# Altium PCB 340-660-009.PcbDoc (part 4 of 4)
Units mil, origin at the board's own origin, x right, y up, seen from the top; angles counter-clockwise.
Board outline 2755.91 x 2755.91 mil, 4 copper layers (Top Layer, Int1 (PWR), Int2 (GND), Bottom Layer), stack 53.912 mil thick; 183 components, 253 nets, 930 pads, 492 vias.
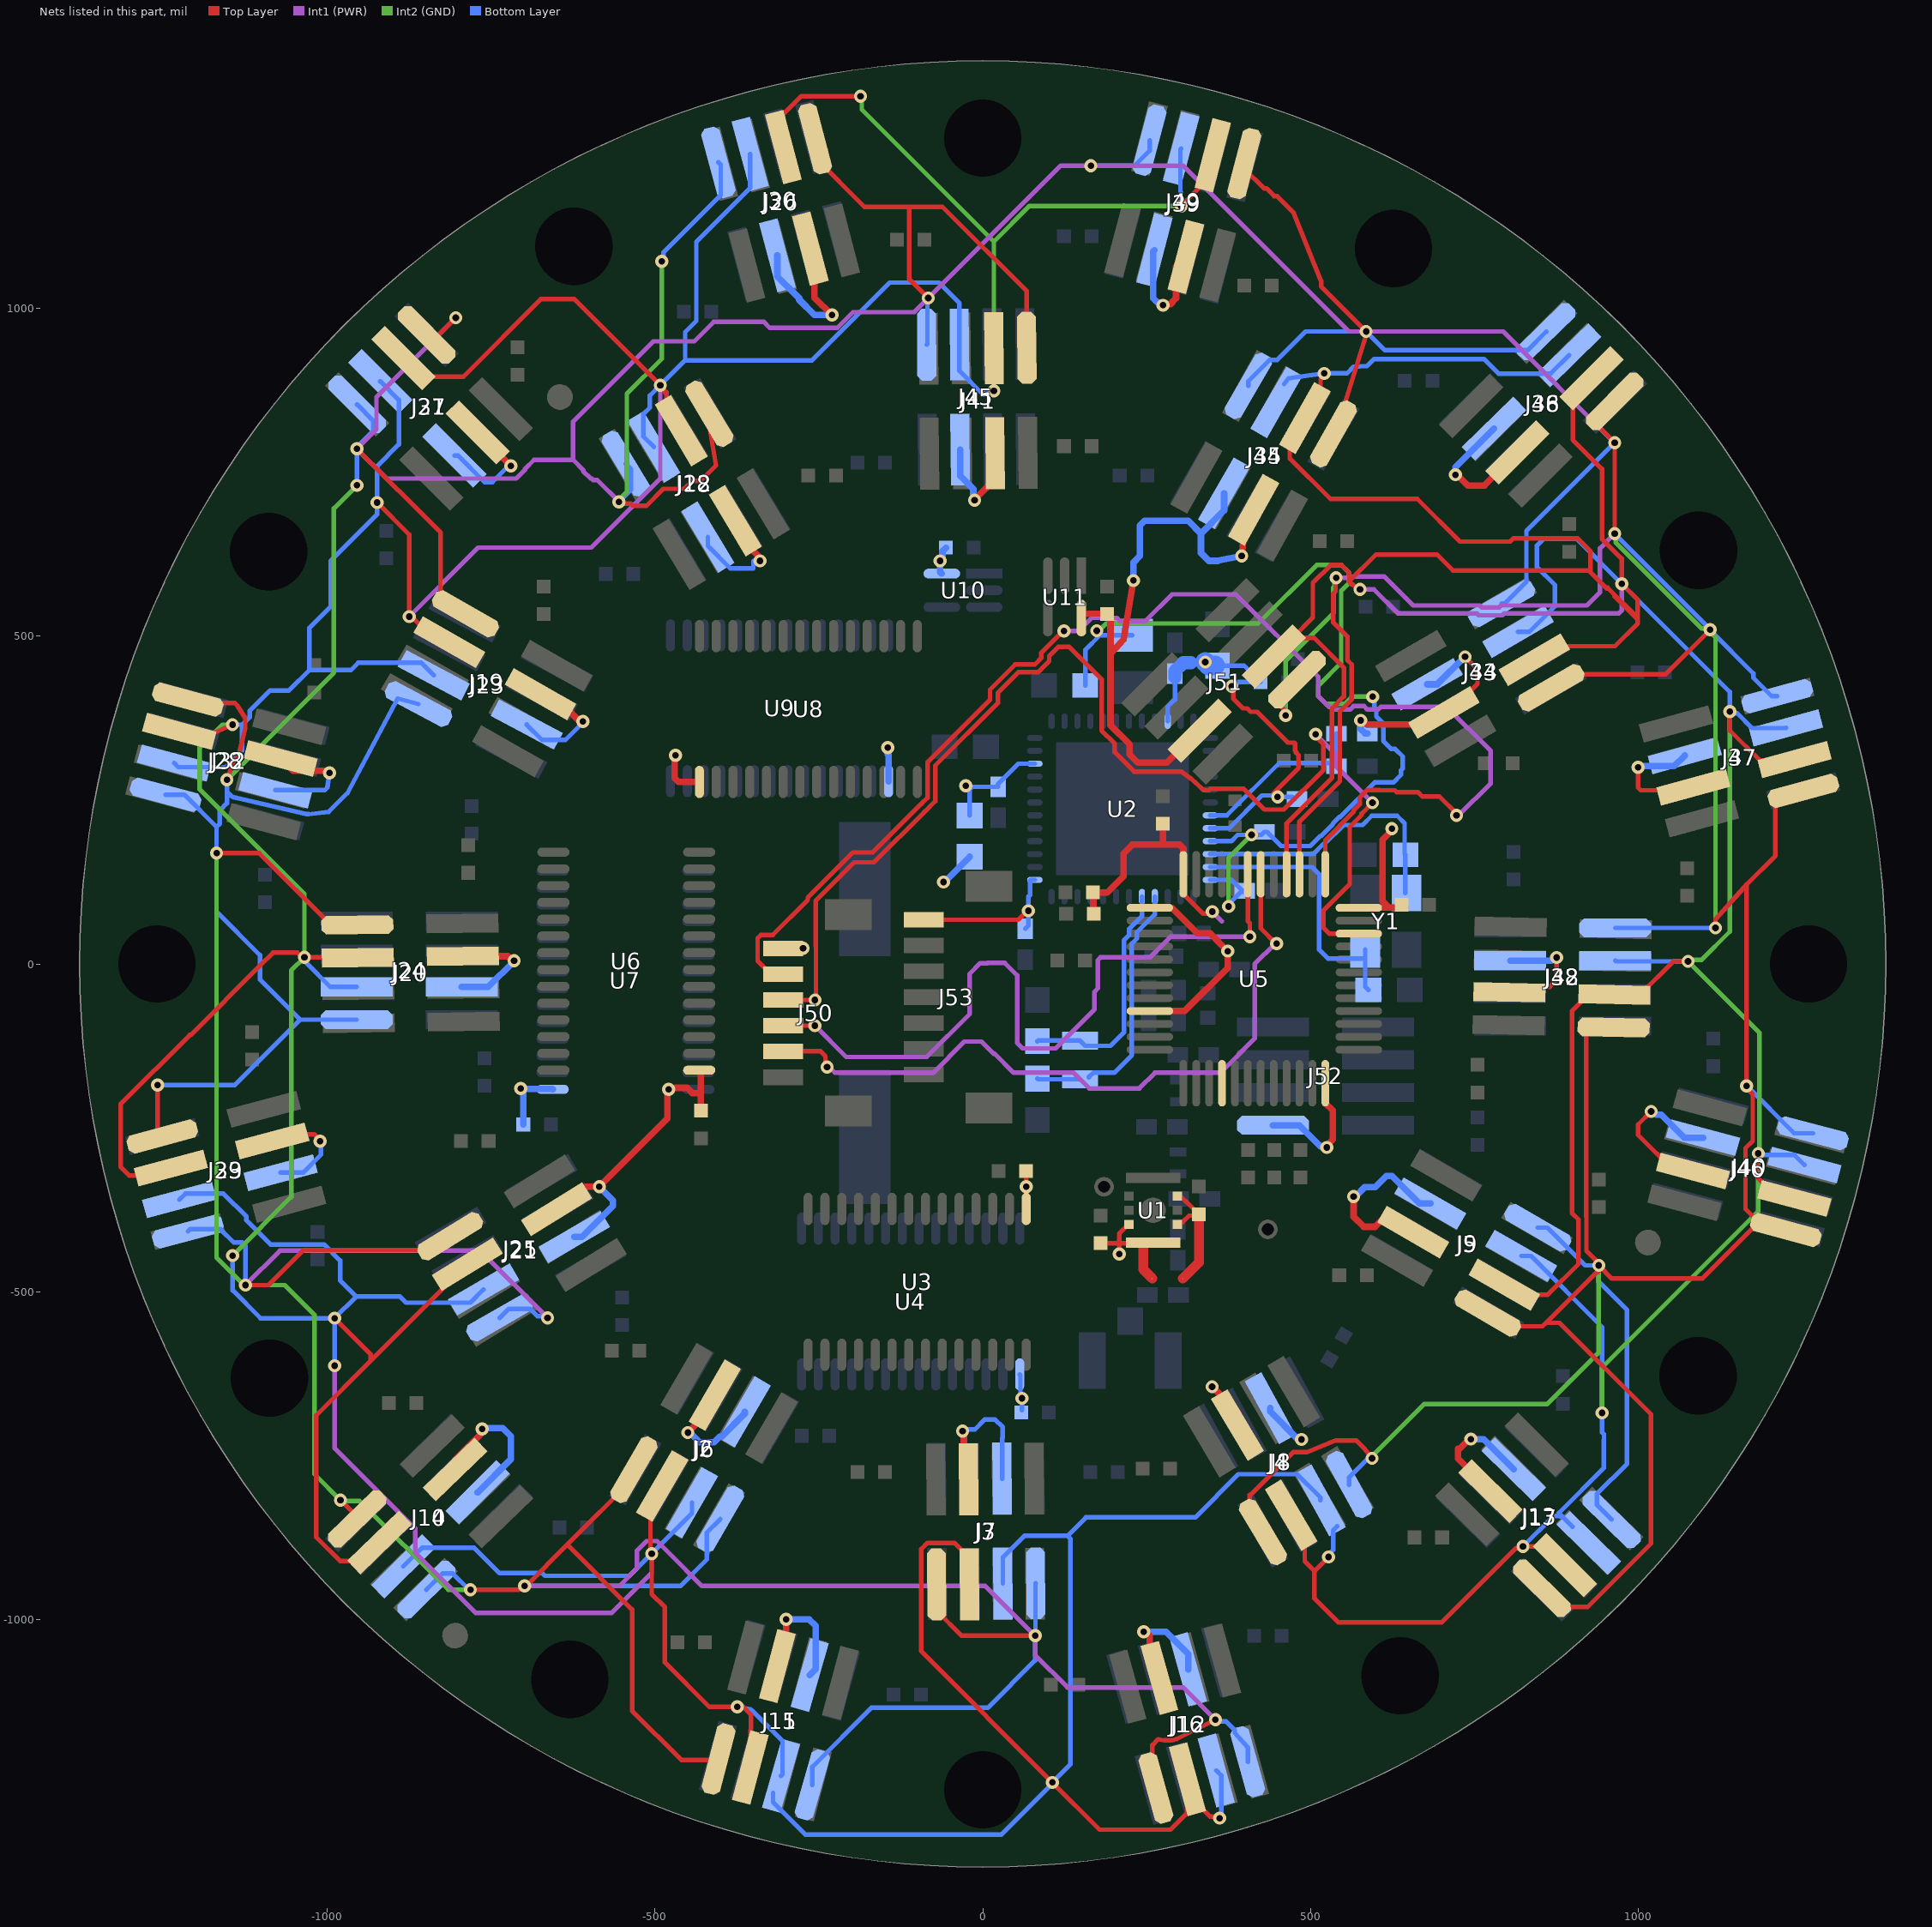
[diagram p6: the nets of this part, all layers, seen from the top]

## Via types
v1: diameter 20, hole 10, Top Layer to Bottom Layer, tented both sides, 489 vias
v2: diameter 20, hole 10, Top Layer to Bottom Layer, 3 vias

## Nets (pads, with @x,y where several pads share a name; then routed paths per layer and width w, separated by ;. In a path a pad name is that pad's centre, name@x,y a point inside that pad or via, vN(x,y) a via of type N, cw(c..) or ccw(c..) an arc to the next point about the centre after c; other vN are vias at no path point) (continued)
SPI_MISO: J2.3 J3.3 J4.3 J5.3 J6.3 J7.3 J8.3 J9.3 J10.3 J11.3 J12.3 J13.3 J14.3 J15.3 J16.3 J17.3 J18.3 J19.3 J20.3 J21.3 J22.3 J23.3 J24.3 J25.3 J26.3 J27.3 J28.3 J29.3 J30.3 J31.3 J32.3 J33.3 J34.3 J35.3 J36.3 J37.3 J38.3 J39.3 J40.3 J41.3 J42.3 J43.3 J44.3 J45.3 J46.3 J47.3 J48.3 J49.3 J51.3 U5.40 | length 20691.8
  Top Layer w7: J29.3@-1238.86,-311.6 -1250.18,-322.92 -1302.08,-322.92 -1315.49,-309.51 -1315.49,-213.91 -1209.93,-108.35 -1208.35,-108.35 -1102.79,-2.79 -1102.79,-2.63 -1082.87,17.29 -1045.81,17.29 -1040.95,12.43 v1@-1037.43,12.43 ; J28.3@-1225.94,354.86 -1173.4,352.26 v1(-1144.77,365) ; v1(-1035,10) -953.93,10 J20.3@-953.48,9.55 ; v1(-989,-540.5) -934.11,-595.39 -934.11,-605.89 ; v1(-924,704) -875,655 v1(-875,530) -871.55,530 -832.49,490.94 J19.3@-814.01,490.94 ; J10.3@-919.96,-882.76 -948.02,-910.83 -980.59,-910.83 -1017,-874.42 -1017,-688.79 -934.11,-605.89 ; J27.3@-855.38,895.88 -792.64,895.88 -674.01,1014.5 -623.5,1014.5 -490.71,881.71 -490.71,880.53 -482.58,872.4 -482.58,836.09 J18.3@-460.14,813.65 ; J21.3@-786.43,-458.21 -934.11,-605.89 ; v1(-492,883) -492,879.48 -484.46,871.94 ; J2.3@-488.94,-796.68 -507.08,-814.82 -507.08,-897.92 v1(-505,-900) -505,-961.5 -485,-981.5 -485,-1065.58 -417.02,-1133.56 v1(-374.7,-1133.56) -365.06,-1133.56 -362.97,-1135.65 -353.6,-1145.3 -353.6,-1148.19 -353.6,-1148.25 J11.3@-354.76,-1225.99 ; J26.3@-304.27,1246.24 -304.27,1296.45 -276.72,1324 v1(-186.5,1324) ; J3.3@-20.38,-946.49 -20.38,-906.43 -43.43,-883.38 -84.44,-883.38 -93.79,-892.73 -93.79,-1048.79 v1(106.21,-1248.79) 178.31,-1320.88 286.53,-1320.88 312.32,-1295.1 J12.3@312.32,-1266.25 ; v1(17,874.34) 17,939.26 J41.3@17.25,939.51 ; v1(302.95,1156.5) 302.95,1156.79 351,1204.83 J49.3@351,1233.85 ; J12.3@312.32,-1243.89 J12.3@312.32,-1266.25 ; v1(361.41,-1303.34) 358.93,-1300.85 346.92,-1300.85 J12.3@312.32,-1266.25 ; J51.3@444.33,468.97 J51.3@472.86,497.51 ; U5.40@463.6,136.8 463.6,214.54 533,283.93 533,389.97 551,407.97 551,452 505.49,497.51 J51.3@472.86,497.51 ; J4.3@470.63,-841.23 491.26,-861.85 491.26,-911.26 506.21,-926.21 ; v1(521,901) 521,897.48 515.5,891.98 515.5,856.86 468.43,809.8 468.43,771.57 530.5,709.5 663.08,709.5 728.08,644.5 804.84,644.5 809.84,649.5 907.52,649.5 927.23,629.79 927.23,597.77 ; v1(527.7,-904.73) 506.21,-926.21 ; v1(575.66,571.5) 572.14,571.5 564.11,579.53 562.5,579.53 558.7,583.34 ; J5.3@795.66,-489.42 810.84,-504.61 862.36,-504.61 909.02,-457.95 909.02,-390.01 899.07,-380.06 899.07,-72.02 924.26,-46.82 1003.19,-46.82 1053.96,3.95 v1(1076.17,3.95) ; v1(824.37,-888.73) 821.89,-891.22 813.78,-891.22 700.52,-1004.48 542.6,-1004.48 506.21,-968.1 506.21,-926.21 ; v1@824.45,-888.81 859.99,-888.81 J13.3@888.43,-917.25 ; J34.3@841.92,464.46 862.32,484.87 964.67,484.87 999.5,519.7 999.5,525.5 ; J48.3@928.97,893.64 900.44,865.1 900.44,799.56 944.83,755.17 944.83,648.51 975,618.35 v1(975,580) 999.5,555.5 999.5,527.92 ; 952.3,572.7 927.23,597.77 ; 953.51,573.91 999.5,527.92 ; 964.09,560.91 999.5,525.5 ; v1(1140,385) 1140,356.23 1185.84,310.39 1237.32,310.39 J47.3@1238.87,311.95 ; v1(1183.37,-289.11) 1180,-315 1180,-323.7 1214.07,-357.76 J46.3@1238.36,-357.76 ; J51.3@472.86,497.51 503.81,528.45 503.81,581.38 531.12,608.7 547.27,608.7 558.7,597.27 558.7,583.34 ; 558.7,583.34 599.86,624.5 693.22,624.5 717.38,600.34 924.66,600.34 927.23,597.77 ; 999.5,525.5 999.5,527.92
  Int1 (PWR) w7: v1(-989,-613) -989,-738.42 -865.96,-861.46 -865.96,-897.96 -773.92,-990 -566.16,-990 -505,-928.84 v1(-505,-900) ; v1(-875,530) -769.79,635.21 -597.21,635.21 -492,740.42 v1(-492,883) ; v1(575.66,571.5) 596.93,571.5 633.42,535 753.66,535 756.74,531.92 792.78,531.92 795.86,535 970.9,535 975,539.1 v1(975,580)
  Int2 (GND) w7: v1(-1144.77,365) -1160,365 -1195,330 -1195,266.79 -1035,106.79 v1(-1035,10) -1055,-10 -1055,-355.5 v1(-1144.5,-445) ; v1(-186.5,1324) -184.5,1322 -184.5,1303.5 17,1102 ; v1(17,874.34) 17,1102 ; v1(302.95,1156.5) 71.5,1156.5 17,1102 ; v1(945,-685) 945,-615.58 1183.37,-377.2 1183.37,-292.01 v1@1186.27,-289.11 ; v1(1076.17,3.95) 1078.32,6.1 1096.67,6.1 1140,49.42 v1(1140,385) ; v1@1077.93,2.19 1185,-104.88 1185,-287.48 v1(1183.37,-289.11)
  Bottom Layer w7: J32.3@-1233.86,306.55 -1227.68,300.37 -1155.07,300.37 -1130,325.44 -1130,365 ; J33.3@-1225.92,-359.88 -1216.54,-350.5 -1158.6,-350.5 -1123.52,-385.58 -1123.52,-390.97 -1086.49,-428 -1004.98,-428 -980.49,-452.49 -980.49,-483.01 -956,-507.5 ; v1(-1144.77,365) -1130,365 ; v1(-1144.5,-445) -1144.5,-498.08 -1102.08,-540.5 v1(-989,-540.5) ; v1(-1035,10) -1032.51,7.51 -1032.51,2.04 -995.47,-35 J24.3@-955.12,-35 ; v1(-989,-613) v1(-989,-540.5) ; J31.3@-919.33,888.97 -890.8,860.44 -890.8,792.76 -924,759.55 v1(-924,704) -924,686 -995,615 -995,545 -1027.31,512.69 -1027.31,448.5 ; J14.3@-884.14,-919.24 -855.67,-890.77 -775.89,-890.77 -737.17,-929.5 -672.02,-929.5 -668.02,-933.5 -538.92,-933.5 -443.66,-838.24 J6.3@-443.66,-821.83 ; J23.3@-837.48,440.52 -856.42,459.46 -952.83,459.46 -963.79,448.5 -1027.31,448.5 ; J25.3@-761.88,-496.71 -782.06,-516.89 -879.92,-516.89 -889.31,-507.5 -956,-507.5 ; J22.3@-501.69,788.76 -517.92,804.98 -517.92,838.91 -508.02,848.8 -508.02,866.98 v1(-492,883) -454,921 ; v1(-374.7,-1133.56) -354.3,-1137 -350.92,-1140.38 -305.58,-1185.72 -305.58,-1236.46 J15.3@-308.02,-1238.91 ; J30.3@-354.88,1235.92 -354.74,1235.77 -354.74,1184.05 -437,1101.79 -437,980.98 -454,963.98 -454,921 ; J15.3@-320,-1265 -320,-1278.86 -270.31,-1328.56 28.4,-1328.56 107.19,-1249.76 107.19,-1247.81 133.6,-1221.4 133.6,-876.6 129.5,-872.5 ; v1(17,874.34) 14.51,871.85 4.23,871.85 0.87,868.49 -35.5,904.86 -35.5,1008.08 -66.92,1039.5 -141.85,1039.5 -260.35,921 -454,921 ; J7.3@30.84,-945.4 30.84,-905.34 63.68,-872.5 129.5,-872.5 ; v1(302.95,1156.5) 302.95,1177 301.6,1178.36 301.6,1242.72 J39.3@302.95,1244.08 ; J16.3@356.31,-1230.52 363.9,-1238.11 363.9,-1300.85 v1(361.41,-1303.34) ; J44.3@460,885 466.43,893.48 479.12,895.23 516.92,900.44 517.48,901 555.8,901 566,911.2 586.2,912.2 597.51,923 764.7,923 787.01,900.68 866.5,900.68 J36.3@894.74,928.92 ; J8.3@515.33,-818.35 515.33,-814.21 479.73,-778.62 390.12,-778.62 324.24,-844.5 157.5,-844.5 129.5,-872.5 ; v1(527.7,-904.73) 527.7,-901.21 534.66,-894.24 534.66,-864.16 J8.3@540.79,-858.03 ; J43.3@816.88,506.71 834,506.71 873.04,545.76 873.04,578.15 845.5,605.69 845.5,638.08 856.92,649.5 905.5,649.5 v1(975,580) 1140,415 v1@1140,385.56 ; J9.3@821.76,-445.57 836.53,-445.57 945,-554.05 v1(945,-685) ; v1(824.37,-888.73) 869.39,-843.71 874.42,-842.44 875.87,-842.44 885.35,-844.03 ; J17.3@899.77,-858.45 885.35,-844.03 ; v1@948,-685 945,-688 945,-714.58 948,-717.58 947.83,-731.88 947.83,-768.89 879.02,-837.7 885.35,-844.03 ; J42.3@965.12,5 966.17,3.95 v1(1076.17,3.95) ; v1(1140,385) 1142.49,382.51 1151.07,382.51 1173.76,359.83 1225.11,359.83 J37.3@1225.62,360.34 ; v1(1183.37,-289.11) 1185.86,-291.6 1238.81,-291.6 J40.3@1253.86,-306.65 ; -1130,365 -1118.54,376.46 -1118.54,386 -1087.29,417.25 -1058.56,417.25 -1027.31,448.5 ; v1(-989,-540.5) -956,-507.5
SPI_SCLK: J2.1 J3.1 J4.1 J5.1 J6.1 J7.1 J8.1 J9.1 J10.1 J11.1 J12.1 J13.1 J14.1 J15.1 J16.1 J17.1 J18.1 J19.1 J20.1 J21.1 J22.1 J23.1 J24.1 J25.1 J26.1 J27.1 J28.1 J29.1 J30.1 J31.1 J32.1 J33.1 J34.1 J35.1 J36.1 J37.1 J38.1 J39.1 J40.1 J41.1 J42.1 J43.1 J44.1 J45.1 J46.1 J47.1 J48.1 J49.1 J51.1 U5.39 | length 21685.5
  Top Layer w7: v1(-1259,-185) -1259,-256.11 J29.1@-1251.81,-263.31 ; J28.1@-1213.01,403.16 -1208.12,398.27 -1141.43,398.27 -1137.33,394.16 -1125.27,375.14 -1125.27,359.82 -1132.88,328.07 -1134.9,320.55 -1145.07,304.28 v1(-1153.27,280.87) ; v1(-1169,169) -1103.97,169 -994.51,59.54 J20.1@-954.17,59.54 ; v1(-1125,-490) -1090,-490 -1036.84,-436.84 -833.86,-436.84 J21.1@-812.68,-415.66 ; v1(-980,-818) -954.73,-843.27 J10.1@-954.73,-846.84 ; v1(-955,786) -827.09,658.09 -827.09,567.13 -794.31,534.36 J19.1@-789.22,534.36 ; J27.1@-848.48,959.69 -847.26,958.47 -831.53,958.47 v1(-804,986) ; v1(-781.66,-954.68) -708.2,-954.68 -702.52,-949 v1(-699,-949) -696.94,-949 -633.97,-886.03 ; v1(-555,705) -552.51,702.51 -537.03,702.51 -533.58,699.06 -512.91,699.06 -487.16,724.81 -455.54,724.81 -443.35,737 -430.5,737 -407,760.5 -417.28,822 J18.1@-417.28,839.4 ; J2.1@-532.21,-771.63 -532.21,-784.28 -633.97,-886.03 ; J11.1@-403.08,-1213.14 -404.44,-1214.5 -460,-1214.5 -535,-1139.5 -535,-985 -633.97,-886.03 ; J26.1@-239.15,1242.26 J26.1@-255.93,1259.04 -255.93,1230.37 -180.57,1155 -112,1155 ; v1(-83,1016) -112,1045 -112,1155 ; J3.1@-70.37,-946.85 -70.37,-986.91 -32.29,-1025 v1(80,-1025) ; J41.1@67.25,939.97 67.25,1026.33 -61.42,1155 -112,1155 ; J12.1@264.14,-1257.25 258.92,-1252.03 258.92,-1191.88 267.79,-1183.01 277.81,-1184.67 288.54,-1184.67 296,-1182.6 v1(355.14,-1153.12) ; J49.1@399.35,1221.12 399.35,1213.07 429.18,1183.24 433,1183.24 444.73,1171.51 448.95,1171.51 474.51,1145.95 516.41,1041.79 516.41,1033.59 v1(585,965) 585,959.2 552.18,853.77 J35.1@535.31,808.63 ; J4.1@427.66,-866.78 407.03,-846.16 407.03,-810 408.89,-810 473.89,-745 494.35,-745 538.69,-726.96 569.96,-726.96 582.75,-739.75 v1(594,-754.31) ; v1(462.27,379.29) 459.78,381.77 459.78,388.2 454.85,393.13 454.85,408.79 J51.1@479.69,433.62 ; U5.39@483.29,136.8 483.29,217.25 545,278.96 545,385 563,403 563,456.97 556.2,463.76 556.2,499.78 535,520.98 535,565.2 538.5,568.7 538.5,588.5 v1(539.2,589.2) ; J5.1@770.64,-532.72 790.83,-552.91 854.09,-552.91 859.5,-547.5 ; J13.1@853.2,-952.72 881.64,-981.16 922.78,-981.16 1019.64,-884.31 1019.64,-687.06 880.08,-547.5 859.5,-547.5 ; J34.1@867.2,421.33 887.6,441.73 1041.73,441.73 v1(1110,510) ; v1@943.36,-465.13 938.25,-470.24 936.76,-470.24 ; J38.1@962.63,-96.81 933.1,-96.81 921,-108.91 921,-385.02 921.08,-385.1 921.08,-437.56 940,-456.48 v1(940,-460) ; v1@964,795 v1(964.33,795.33) ; v1(964.33,656.59) v1(964.33,795.33) ; J48.1@964.33,858.29 940.68,834.64 940.68,818.98 v1(964.33,795.33) ; v1(1118,55) 1118,68.14 1166.87,122.27 ; v1@1165.5,-189.52 1174.89,-198.91 1174.89,-270.02 1163.87,-281.03 1163.87,-373.87 1182.86,-392.86 J46.1@1190.58,-392.86 ; v1(1165.5,-186) 1165.5,120.75 1209.56,164.81 1209.56,240.63 1232.64,263.71 J47.1@1252.02,263.71 ; J46.1@1200.32,-402.61 1175.41,-402.61 1098.02,-480 960,-480 v1(940,-460) ; 859.5,-547.5 936.76,-470.24 ; 936.76,-470.24 937.51,-469.49 937.51,-462.49 v1(940,-460)
  Int1 (PWR) w7: v1(-1125,-490) -1072.5,-437.5 -766.51,-437.5 v1(-664,-540.01) ; v1(-804,986) -925,865 -925,816 v1(-955,786) -909.5,740.5 -711.92,740.5 -698.3,754.12 -698.3,755.44 -684.68,769.07 -625,769.07 ; v1(-699,-949) -554.42,-949 -527.5,-922.08 -527.5,-894.92 -513.08,-880.5 -496.92,-880.5 -479.24,-898.18 -479.24,-898.34 -428.58,-949 4,-949 v1(80,-1025) 80,-1054.58 129.27,-1103.85 305.86,-1103.85 v1(355.14,-1153.12) ; v1(-555,705) -588.28,738.28 -594.21,738.28 -596.43,740.5 -598.08,740.5 -609.5,751.92 -609.5,753.57 -625,769.07 ; v1(539.2,589.2) 539.35,589.04 563.2,589.04 565.15,591 567.58,591 612.74,591 656.74,547 758.63,547 761.71,543.92 787.81,543.92 790.89,547 921.81,547 941.83,567.02 941.83,634.09 v1(964.33,656.59) ; v1@964,795 794,965 v1(585,965) 558.58,965 305.58,1218 v1(165,1218) 119,1218 v1(-83,1016) -104.49,994.51 -197.92,994.51 -221.92,970.5 -324.92,970.5 -333.92,979.5 -410.5,979.5 -440,950 -502.58,950 -625,827.58 -625,769.07
  Int2 (GND) w7: v1@-1169,164 -1169,-448.08 -1127.08,-490 v1(-1125,-490) -1065,-490 -1019.76,-535.24 -1019.76,-778.24 -978.5,-819.5 -950.5,-819.5 -815.32,-954.68 v1(-781.66,-954.68) ; v1(-1153.27,280.87) -990,444.15 -990,694.91 v1(-954.69,730.23) ; v1(-555,705) -555,708.52 -543,720.52 -543,870.09 -489.62,923.47 v1(-489.62,1072.06) ; v1(462.27,379.29) 462.27,462.27 535,535 535,574.39 536.71,576.1 536.71,586.71 v1(539.2,589.2) ; v1(594,-754.31) 594,-751 673.21,-671.79 860.79,-671.79 940,-592.58 v1(940,-460) ; v1(964.33,656.59) 965.74,655.18 965.74,643.01 1096.88,511.87 1108.13,511.87 v1(1110,510) 1110,506.48 1118,498.48 v1(1118,55)
  Bottom Layer w7: v1(-1259,-185) -1141.5,-185 -1041.5,-85 ; J32.1@-1246.78,258.25 -1218.23,258.25 -1169,209.03 ; J33.1@-1212.98,-408.18 -1209.57,-404.77 -1162.99,-404.77 -1142.62,-425.14 -1129.86,-425.14 -1125,-430 v1(-1125,-490) ; v1(-1153.27,280.87) -1153.27,263 ; -1139.4,253.4 -1142.74,254.16 cw(c-1141.18,260.98) -1145.84,255.76 cw(c-1078.84,330) -1149.56,259.29 -1153.27,263 ; -1139.36,253.39 -1031.68,228.6 ccw(c-1029.78,236.88) -1028.82,228.43 -998.08,231.92 -969.22,260.78 -892.6,404.95 J23.1@-860.94,396.37 ; J24.1@-955.12,-85 -1041.5,-85 ; v1(-955,786) -954.84,785.84 -954.84,730.38 v1(-954.69,730.23) ; v1@-954.69,786.31 -954.69,788.76 -930.08,813.36 -930.08,829.01 J31.1@-954.69,853.62 ; J14.1@-848.86,-954.68 -824.35,-930.17 -808.56,-930.17 -784.05,-954.68 v1(-781.66,-954.68) ; J25.1@-736.88,-540.01 -723.01,-526.14 -690.63,-526.14 -679.25,-537.52 -666.49,-537.52 v1(-664,-540.01) ; v1(-699,-949) -461.42,-949 -421.02,-908.6 -421.02,-867.55 J6.1@-400.43,-846.96 ; v1(-555,705) -536.47,723.53 -536.47,754.95 J22.1@-544.58,763.06 ; v1(-489.62,1072.06) -487.13,1074.55 -487.13,1085.64 -399.77,1172.99 -399.77,1219.57 J30.1@-403.18,1222.98 ; J15.1@-259.96,-1252.67 -259.96,-1224.99 -169.93,-1134.96 7.62,-1134.96 80,-1062.58 80,-1025.84 v1@80.84,-1025 ; J45.1@-85.5,944.65 -84.38,945.77 -84.38,1014.62 v1(-83,1016) ; v1(80,-1025) 80.57,-1024.43 80.57,-945.31 J7.1@80.84,-945.04 ; v1(165,1218) 231.88,1218 254.6,1240.73 J39.1@254.6,1256.82 ; v1(355.14,-1153.12) 357.63,-1155.61 371.05,-1155.61 384.69,-1169.25 384.69,-1173.14 384.75,-1173.2 404.5,-1195.34 J16.1@404.5,-1217.16 ; J44.1@405.11,881.88 405.11,888.76 438.04,921.69 449.27,921.69 492.58,965 v1(585,965) 613.6,936.4 831.52,936.4 J36.1@859.75,964.64 ; J8.1@559.22,-794.4 559.22,-783.21 585.63,-756.8 591.51,-756.8 v1(594,-754.31) ; J43.1@791.88,550.01 796.71,550.01 829.64,582.94 829.64,660.64 v1(964.33,795.33) ; J9.1@846.76,-402.27 861.53,-402.27 919.25,-460 v1(940,-460) 940,-485 983.14,-528.14 983.14,-762.81 937.1,-808.85 937.1,-825.07 J17.1@959.71,-847.68 ; v1(964.33,656.59) 964.33,656.13 v1@1110,510.46 ; J42.1@965.12,55 v1(1118,55) ; v1(1110,510) 1110,509.05 1175.93,443.12 1175.93,436.49 1203.87,408.55 J37.1@1212.37,408.55 ; v1(1165.5,-186) 1165.74,-186 1238.1,-258.36 J40.1@1266.84,-258.36 ; -1169,209.03 v1(-1169,169) -1169,79.58 -1102.79,13.37 -1102.79,-23.71 -1041.5,-85 ; -1169,209.03 -1164.05,213.98 -1164.05,234.36 -1153.27,245.13 -1153.27,263
SWCLK: J50.2 U5.37 | length 2023.9
  Top Layer w7: J50.2@-304.41,-15.55 -323.11,-15.55 -343.42,4.76 -343.42,39.15 -338.44,44.13 -320.35,44.13 -266.87,97.61 -266.87,101.18 -198.05,170 -167.88,170 -93.43,244.45 -93.31,244.45 -84.29,253.47 -84.29,307.68 11.03,403 11.03,418.41 49.61,457 79.58,457 89.5,466.92 89.5,474.8 105.92,491.21 106,491.21 122.9,508.11 v1(124.01,508.11) ; U5.37@522.66,136.8 522.66,188.64 565.99,231.98 565.99,234.22 575.2,243.44 575.2,254.04 586.63,265.47 605.22,265.47 605.69,265 628.77,265 631.66,262.11 645.86,262.11 ; 645.88,262.13 663.85,262.13 670.5,255.48 696.84,255.48 722.91,229.41 v1(722.91,226.74)
  Int1 (PWR) w7: v1(124.01,508.11) 146.14,508.11 165.91,527.89 204.57,527.89 209.42,523.04 248.08,523.04 289.04,564 386,564 512,438 512,408.42 528.42,392 531.31,392 535.11,388.2 560.63,388.2 565.79,393.37 581.95,393.37 587.11,388.2 603.27,388.2 607.07,392 708,392 775,325 775,275.32 726.42,226.74 v1(722.91,226.74)
SWD: J50.3 U5.34 | length 1843.8
  Top Layer w7: J50.3@-304.41,-54.92 v1(-255.9,-54.92) -254.56,-53.58 -254.56,26.99 -254.87,27.3 -254.87,96.21 -196.08,155 -165.91,155 -88.46,232.45 -88.34,232.45 -72.29,248.5 -72.29,302.71 23.03,398.03 23.03,413.44 54.58,445 84.55,445 101.5,461.95 101.5,469.83 113.3,481.62 113.38,481.62 115.67,483.91 131.74,483.91 181.49,434.17 181.49,355.89 201.23,336.15 201.23,323.05 230.71,293.57 303.43,293.57 316.54,283.81 316.81,283.81 318.15,282.48 334.49,267.36 336.75,265.1 340.09,265.1 345,265 347.19,267.19 398.36,267.19 430.05,235.5 459.52,235.5 520,295.98 520,335.01 508,347.01 v1(508,350.53) ; U5.34@573.84,46.25 528.75,46.25 520,55 520,81.68 560,121.68 560,209.01 577.99,227.01 577.99,229.25 v1(594.7,245.97)
  Int1 (PWR) w7: v1(508,350.53) 539.16,319.36 539.16,301.51 v1(594.7,245.97)
  Bottom Layer w7: v1(594.7,245.97) v1@594.7,247.07
TIA_ENBL: U5.16
USART1_RX: J50.4 U5.43 | length 1149.7
  Top Layer w7: J50.4@-304.41,-94.29 v1(-256,-94.29) ; U5.43@404.55,136.8 404.55,65.47 407.67,62.35 v1(407.67,41.47)
  Int1 (PWR) w7: v1(-256,-94.29) -208.33,-141.96 -85.45,-141.96 -20,-76.51 -20,-15.2 -3.68,1.13 7.2,1.13 7.57,1.5 33.66,1.5 52.5,-17.34 52.5,-120.44 60.88,-128.82 110.97,-128.82 170.5,-69.29 170.5,-42.49 175.67,-37.32 175.67,5.9 179.77,10 255,10 286.47,41.47 v1(407.67,41.47)
USART1_TX: J50.5 U5.42 | length 1098.7
  Top Layer w7: J50.5@-304.41,-133.66 -304.04,-133.29 -247.54,-133.29 -240.06,-140.77 -240.06,-154.78 v1(-237.58,-157.26) ; U5.42@424.23,136.8 424.23,54.29 447.58,30.94 v1(448.56,30.94)
  Int1 (PWR) w7: v1(-237.58,-157.26) -234.06,-157.26 -225.36,-165.96 -75.51,-165.96 -28.05,-118.5 -1.95,-118.5 16.41,-136.87 18.02,-136.87 47.12,-165.96 138.69,-165.96 162.61,-189.88 238.93,-189.88 262.85,-165.96 362.73,-165.96 415,-113.7 415,0 445.94,30.94 v1(448.56,30.94)
V3.3V: C1.2 C26.2 C27.2 C28.2 C31.2 C32.2 C33.2 C34.2 C35.2 C36.2 J2.4 J3.4 J4.4 J5.4 J6.4 J7.4 J8.4 J9.4 J10.4 J11.4 J12.4 J13.4 J14.4 J15.4 J16.4 J17.4 J18.4 J19.4 J20.4 J21.4 J22.4 J23.4 J24.4 J25.4 J26.4 J27.4 J28.4 J29.4 J30.4 J31.4 J32.4 J33.4 J34.4 J35.4 J36.4 J37.4 J38.4 J39.4 J40.4 J41.4 J42.4 J43.4 J44.4 J45.4 J46.4 J47.4 J48.4 J49.4 J50.1 J51.4 J52.1 L1.2 R1.2 R52.2 SJ1.2 U1.3 U1.8 U3.1 U4.1 U5.1 U5.9 U5.24 U5.36 U5.48 U6.1 U7.1 U8.1 U9.1 U10.5 U11.5 | length 7813.7
  Top Layer w7: J29.4@-1084.09,-270.11 -1073.98,-260 -1020,-260 -1011.27,-268.73 v1(-1011.27,-270.5) ; J50.1@-304.41,23.82 v1(-274.06,23.82) ; U3.1@66.34,-373.78 v1(66.34,-340) 66.34,-319.66 C31.2@71,-315 ; C1.2@180,-426 208.29,-426 ; v1(208.29,-442.53) 208.29,-426 ; U1.3@223.09,-397.44 222.6,-397.44 208.29,-411.75 208.29,-426 ; U1.8@236.57,-426 208.29,-426 ; U5.48@306.12,136.8 306.12,106.59 335.71,77 347.49,77 v1(350.26,79.77) ; J34.4@703.67,383.45 711.13,383.45 755,427.33 755,449.55 v1(736.02,468.53) ; J38.4@803.53,-43.33 811.86,-35 865,-35 875.62,-24.38 v1(875.62,9.88) ; v1(1000,300) 1000,269.1 1004.1,265 1079.46,265 J47.4@1084.27,269.81 ; v1(1020,-225) 1000,-245 1000,-261.06 1055.12,-316.18 J46.4@1083.62,-316.18
  Top Layer w10: J28.4@-1071.14,313.45 -1052.48,294.78 -1002.71,294.78 -999.28,291.35 v1(-996.57,291.35) ; J10.4@-804.82,-771.32 -804.82,-756.53 -765.86,-717.56 -765.86,-711.54 v1(-763.94,-709.63) ; J20.4@-793.26,11.76 -724.46,11.76 -717.71,5 v1(-715,5) ; J27.4@-770.72,810.93 -770.72,810.72 v1(-720,760) ; J19.4@-674.87,411.48 -656.48,411.48 -615,370 v1(-610,370) ; J21.4@-607.6,-341.98 -605.62,-340 v1(-585,-340) -481,-236 -481,-193.26 v1(-479.26,-191.52) -477.35,-189.61 -469.31,-189.61 -468.7,-189 -451.3,-189 -442.88,-197.42 -430,-197.42 -430,-163.83 -431.75,-162.09 U6.1@-432.56,-162.09 ; v1@-470,320 -470,319.23 v1(-468.92,318.15) -470,317.07 -470,283.42 -464.14,277.56 U8.1@-432.36,277.56 ; v1(-450,-715) -408.66,-673.66 J2.4@-408.66,-658.01 ; C33.2@-430,-224 -430,-200 ; J18.4@-377.61,676.3 -377.61,657.61 -340,620 v1(-340,615) ; J11.4@-313.55,-1071.15 -300,-1057.59 v1(-300,-1000) ; J26.4@-263.23,1091.34 -256.6,1084.71 -256.6,1016.6 v1(-230,990) ; v1(-30.78,-712.75) -28.87,-714.66 -28.87,-778.93 J3.4@-21.54,-786.26 ; v1(-12.49,707.49) -10,709.98 -10,710.58 18.72,739.3 J41.4@18.72,779.28 ; U11.5@150.59,527.71 150.59,531.78 152.81,534 C36.2@190,534 194.99,529.01 194.99,473.46 ; R52.2@169.27,76.8 168.76,77.32 168.76,108.51 C27.2@168.25,109.03 190.03,109.03 215,134 215,168.58 228.41,181.99 275,181.99 ; v1(230,585) 214.86,494.85 194.99,473.46 ; v1(245.81,-1018.83) 248.52,-1018.83 254.69,-1025 255,-1025 255,-1074.98 J12.4@269.5,-1089.48 ; U5.9@254.94,-71.86 308.14,-71.86 373.99,-6.01 373.99,20 373.51,20 346.75,46.77 327.16,46.77 288.66,85.27 255.29,85.27 U5.1@254.94,85.62 ; C26.2@275,214 275,181.99 ; v1(275,1005) 276.76,1006.76 286.76,1006.76 289.47,1009.47 289.47,1010.27 295,1015.8 295,1063.74 J49.4@310.17,1078.91 ; U5.48@306.12,136.8 306.12,176.13 300.26,181.99 275,181.99 ; J51.4@331.03,355.67 329.35,355.67 280.74,307.07 236.3,307.07 224,319.37 224,335.09 194.99,364.1 194.99,473.46 ; v1(350,-645) 388.73,-683.73 J4.4@388.73,-703.5 ; v1(395.24,622.34) 397.51,644.88 J35.4@413.51,693.12 ; U5.24@522.66,-182.1 522.66,-212.11 534.21,-223.67 534.21,-268.08 525,-277.29 v1(525,-280) ; v1(565.92,-355) 565.92,-385.62 581.3,-401 598.7,-401 607.21,-392.48 640.13,-392.48 J5.4@656.91,-409.27 ; U5.36@573.84,85.62 574.18,85.97 620,85.97 ; v1(576.81,371.65) 579.52,371.65 585.96,365.21 685.42,365.21 J34.4@703.67,383.45 ; v1(624.24,206.49) 624.24,203.79 610,189.54 610,95.97 620,85.97 ; C28.2@644.97,85.97 620,85.97 ; v1(721.19,746.35) 723.85,746.35 740.2,730 765.37,730 J48.4@815.69,780.32 ; v1(745,-725) 742.29,-725 727.29,-740 725,-740 725,-754.56 J13.4@774.76,-804.32
  Top Layer w15: SJ1.2@258.76,-480 245,-466.24 245,-427.32 243.5,-425.83 260.01,-425.42 261.79,-425.37 U1.8@260,-425
  Int1 (PWR) w7: v1(350.26,79.77) 365,65.03
  Bottom Layer w7: J32.4@-1079.07,265.14 -1007,265.14 -1004.1,265.14 -1000,269.24 v1(-996.57,291.35) ; J33.4@-1071.14,-318.41 -1037.12,-318.41 -1009.75,-291.05 -1009.75,-272.02 v1(-1011.27,-270.5) ; J31.4@-806.03,775.67 -800.65,775.67 -759.98,735 -748.27,735 -723.27,760 v1(-720,760) ; J23.4@-695.98,365.33 -672.47,341.81 -636.81,341.81 -610,368.62 v1(-610,370) ; J22.4@-419.35,651.3 -419.35,637.79 -385,603.44 -350,603.44 -350,615 v1(-340,615) ; v1(-30.78,-712.75) -28.3,-710.26 -12.07,-710.26 2.89,-695.3 19.05,-695.3 30.47,-706.72 30.47,-722.87 29.67,-723.67 J7.4@29.67,-785.17 ; U4.1@56.34,-626.22 57.64,-627.52 57.64,-660.59 v1(59.78,-662.73) ; v1@57.97,-663 59.78,-664.81 C32.2@59.78,-680.78
  Bottom Layer w10: J24.4@-794.88,-35 -754.53,-35 -715,4.53 v1(-715,5) ; J14.4@-770.59,-806.19 -720,-755.6 -720,-733.42 ; v1(-763.94,-709.63) -762.74,-708.42 -732.27,-708.42 -719.97,-720.73 -719.97,-733.4 ; C34.2@-701,-245 -701,-196.71 -705,-192.71 v1(-705,-190) -704.33,-190.67 -656.89,-190.67 U7.1@-656.22,-191.34 ; J25.4@-623.12,-416.59 -611.59,-416.59 -564.14,-369.14 -564.14,-360.86 v1(-585,-340) ; v1(-450,-715) -447.29,-715 -432.29,-730 -409.81,-730 -401.2,-721.39 -398.32,-721.39 -363.12,-686.19 J6.4@-363.12,-683.3 ; J30.4@-313.41,1081.14 -313.41,1049.19 -280,1015.78 -280,1013.39 -256.61,990 v1(-230,990) ; v1(-300,-1000) -265,-1000 -255,-1010 -255,-1075.95 J15.4@-263.91,-1084.86 ; v1(-145,330) -145,320 -143.66,318.66 U9.1@-143.66,278.78 ; U10.5@-62.29,595.59 -62.78,595.59 -65,597.81 v1(-65,615) -65,617.71 -61.5,621.21 -61.5,629.5 C35.2@-56,635 ; v1(-60,125) -55,130 -53.5,130 L1.2@-20,163.5 ; J45.4@-34.5,784.73 -34.5,744.63 -14.41,724.54 -14.41,709.41 v1(-12.49,707.49) ; v1(230,585) 230,612.33 240,622.33 240,669.14 246.86,676 313.42,676 333,656.42 ; v1(245.81,-1018.83) 279.45,-1018.83 313.49,-1052.87 J16.4@313.49,-1076.12 ; J39.4@262.12,1089.14 260,1087.01 260,1015.86 265.86,1010 267.29,1010 272.29,1005 v1(275,1005) ; J44.4@368.29,718.12 368.29,691.71 333,656.42 ; v1(395.24,622.34) 358.56,615 345.3,615 333,627.3 333,656.42 ; J8.4@438.56,-677.7 438.56,-682.76 479.39,-723.59 484.36,-723.59 v1(486.27,-725.5) ; J52.1@442.66,-246.13 483.02,-246.13 514.97,-278.09 523.09,-278.09 v1(525,-280) ; v1(565.92,-355) 568.63,-355 582.92,-340.71 598.75,-340.71 616.15,-323.3 624.43,-323.3 666.59,-365.46 J9.4@682.99,-365.46 ; v1(576.81,371.65) 576.81,358.35 583.62,351.54 R1.2@586.99,351.54 ; J43.4@678.12,426.59 693.49,426.59 735.42,468.53 v1(736.02,468.53) ; v1(721.19,746.35) 721.19,757.71 J36.4@780.27,816.8 ; v1(745,-725) 764.38,-725 J17.4@810.39,-771.01 ; J42.4@804.88,5 868.04,5 872.92,9.88 v1(875.62,9.88) ; v1(1000,300) 1001.91,301.91 1055.16,301.91 J37.4@1071.12,317.87 ; v1(1020,-225) 1022.71,-225 1027.71,-230 1035.39,-230 1070.45,-265.06 J40.4@1099.12,-265.06
  other v1: 373.99,19.53
V_MONITOR: R1.1 R2.2 U2.43 | length 270.6
  Bottom Layer w7: U2.43@347.22,226.69 372.52,226.69 452.37,306.54 539.74,306.54 R1.1@539.74,351.54
VDDR: C10.1 C11.1 C12.1 L2.2 U2.45 U2.48 | length 1625
  Int2 (GND) w7: v1(173.99,508.39) 177.51,508.39 188.54,519.43 420.3,519.43 509.57,608.7 547.27,608.7 558.7,597.27 558.7,581.12 547,569.42 547,459.58 512,424.58 512,408.42 523.42,397 552.45,397 563.16,407.7 v1(595.19,407.7) ; v1(375.02,87.7) 375.02,161.71 v1(410.22,196.91)
  Bottom Layer w7: C10.1@156.5,425 156.5,479.03 v1@178.96,501.5 ; v1(173.99,508.39) 173.99,506.48 v1@178.96,501.5 ; L2.2@228.37,501.54 228.33,501.5 v1@178.96,501.5 ; U2.48@347.22,128.27 379.63,128.27 C12.1@396.09,111.82 ; U2.45@347.22,187.32 379.36,187.32 388.95,196.91 404.22,196.91 408.84,201.54 v1@410.22,201.54 ; v1(375.02,87.7) v1@375.02,90.75 ; C12.1@397.61,110.29 394.56,110.29 v1@375.02,90.75 ; C12.1@399.74,111.54 395.81,111.54 v1@375.02,90.75 ; v1(410.22,196.91) v1@410.22,201.54 ; v1(595.19,407.7) 597.68,405.22 597.68,391.42 600.49,388.6 600.49,377.62 611.24,366.87 611.24,340.1 623.34,328 629.35,328 640.77,316.58 640.77,297.99 638.24,295.46 638.24,288.42 626.81,277 598.16,277 545.16,224 543.86,224 534.5,214.64 534.5,213.25 516.12,194.88 514.74,194.88 499.86,180 455.22,180 433.68,201.54 C11.1@429.74,201.54 425.12,196.91 414.85,196.91 v1@410.22,201.54
VDDS: C5.1 C6.1 C7.1 C8.1 C9.1 J53.1 L1.1 R57.2 U2.13 U2.22 U2.34 U2.44 | length 1058.6
  Top Layer w7: J53.1@-89.88,67.41 54.34,67.41 67.97,81.05 v1(69.7,81.05) ; v1(380.06,423.57) 382.55,421.08 382.55,404.45 397.05,389.95 403.41,389.95 408.61,384.75 418.67,384.75 465.9,337.52 475.49,337.52 476.82,336.18 476.82,325.2 478,324.02 478,322.28 482,318.28 482,298.97 444.01,260.99 v1(450,255)
  Bottom Layer w7: v1(-25.76,271.82) v1@-20,266.06 ; L1.1@-20,226.5 v1@-20,266.06 ; C5.1@65,53.62 69.7,58.32 v1(69.7,81.05) ; v1@69.61,81.05 69.61,102.46 72.2,105.05 72.2,127.14 73.33,128.27 U2.13@79.51,128.27 ; U2.22@79.51,305.43 54.26,305.43 23.37,274.54 C6.1@23.37,270.16 -15.9,270.16 v1@-20,266.06 ; U2.34@282.26,370.39 282.26,392.43 293.37,403.54 C9.1@293.37,434.04 ; U2.44@347.22,207.01 375.84,207.01 426,257.17 447.83,257.17 v1(450,255) 472.34,255 C7.1@475.81,251.54 ; C8.1@358.37,455.04 398.96,455.04 R57.2@424,430 390.01,430 383.58,423.57 v1(380.06,423.57)
  Bottom Layer w20: C9.1@293.37,437.17 293.37,446.85 305.92,459.41 317.58,459.41
  Bottom Layer w30: v1(339.6,460.5) 344.56,455.54 C8.1@354.67,455.54
VHARV: C2.2 SJ1.1 U1.4 U1.6 | length 192
  Top Layer w7: U1.4@296.91,-397.44 300.3,-394.05 304.94,-394.05 315,-383.99 327.58,-383.99 C2.2@329.78,-381.79 311.78,-363.79 311.21,-363.79 304.94,-357.52 300.3,-357.52 U1.6@296.91,-354.13
  Top Layer w15: SJ1.1@305.36,-480 329.78,-455.59 C2.2@329.78,-381.79
X24M_N: C24.1 U2.46 Y1.3 | length 432.1
  Bottom Layer w7: U2.46@347.22,167.64 504.47,167.64 519.71,182.88 521.48,182.88 550.6,212 579.7,212 593.7,225.99 632.32,225.99 643.74,214.57 643.74,167.65 C24.1@644.86,166.54 644.86,161.54 Y1.3@644.86,108.31
X24M_P: C23.1 U2.47 Y1.1 | length 423.3
  Bottom Layer w7: U2.47@347.22,147.95 502.29,147.95 513.37,136.87 513.37,21.54 526.67,8.23 Y1.1@581.87,8.23 ; Y1.1@583.5,21.69 583.5,-34.59 C23.1@588.42,-39.51
X32K_Q1: C37.2 U2.4 Y2.1 | length 414.9
  Bottom Layer w7: C37.2@83.37,-174.97 84.39,-175.99 Y2.1@148.37,-175.99 Y2.1@135,-175.99 ; Y2.1@161.84,-172.99 168.87,-165.96 200.87,-165.96 227.49,-139.34 227.49,31.09 235.23,38.83 235.23,48.2 262.58,75.55 262.58,97.68 U2.4@262.58,102.68
X32K_Q2: C25.2 U2.5 Y2.2 | length 362.9
  Bottom Layer w7: C25.2@83.37,-117.96 84.39,-116.94 Y2.2@148.37,-116.94 156.43,-125 195,-125 215.49,-104.51 215.49,36.06 223.23,43.8 223.23,53.17 242.89,72.84 U2.5@242.89,102.68
pads on no net: J50. J53.8 MH1.1 MH2.1 MH3.1 MH4.1 MH5.1 MH6.1 MH7.1 MH8.1 MH9.1 MH10.1 MH11.1 MH12.1 U1.5 U2.11 U2.12 U2.18 U2.19 U2.20 U2.21 U2.28 U2.29 U2.30 U2.31 U2.32 U2.36 U2.37 U2.38 U2.39 U2.40 U2.41 U2.42 U3.2 U3.3 U3.13 U4.2 U4.3 U4.13 U5.2 U5.3 U5.4 U5.5 U5.6 U5.20 U5.31 U5.32 U5.33 U5.38 U5.45 U6.2 U6.3 U6.13 U7.2 U7.3 U7.13 U8.2 U8.3 U8.13 U9.2 U9.3 U9.13 XFID1.0 XFID1.1 XFID2.0 XFID2.1 XFID3.0 XFID3.1

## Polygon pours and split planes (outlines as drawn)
V3.3V on Int1 (PWR) "V3.3V_L02_P003" (solid, remove dead copper, pour order 3): -1377.95,0 ccw(c0,0) 0,-1377.95 ccw(c0,0) 1377.95,0 ccw(c0,0) 0,1377.95 ccw(c0,0)
VDDS on Int1 (PWR) "VDDS_L02_P002" (solid, pour order 2): 275,480 280,485 413.55,485 525,373.55 525,245 335,55 -45,55 -45,360 80,485
GND on Bottom Layer "GND_L04_P000" (solid, remove dead copper, pour order 0): 130,-665 135,-660 320,-660 495,-540 570,-400 557.3,254.19 488.03,314.34 -104.5,289.39 -115,-330 70,-370 60,-665
GND on Int2 (GND) "GND_L03_P001" (solid, remove dead copper, pour order 1): -1377.95,0 ccw(c0,0) 0,-1377.95 ccw(c0,0) 1377.95,0 ccw(c0,0) 0,1377.95 ccw(c0,0)

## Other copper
Top Layer:
  region net V3.3V: 292.43,-511.03 262.55,-480 292.43,-448.97 225.09,-448.97 225.09,-511.03
  region net VHARV: 334.91,-511.03 304.69,-511.03 275.82,-479.9 306.75,-448.97 334.91,-448.97
Bottom Layer:
  region net GND: 608.37,66.54 608.37,181.54 538.37,181.54 528.37,171.54 528.37,76.54 538.37,66.54
  region net GND: 393.37,501.54 393.37,544.8 323.37,544.8 323.37,501.54
  region net GND: 625,50 625,-65 695,-65 705,-55 705,40 695,50
  region net NetC14_2: 357.99,-56.46 326.99,-56.46 326.99,64.54 345.37,64.54 357.99,51.91
  region net NetC16_1: 312.99,-184.46 281.99,-184.46 281.99,-70.46 312.99,-70.46 356.37,-70.46 356.37,-101.46 312.99,-101.46
  region net VDDS: 323.37,476.54 418.37,476.54 418.37,416.54 323.37,416.54
  region net DCDC_SW: 267.37,358.54 267.37,442.54 258.37,451.54 198.37,451.54 198.37,401.54 203.37,396.54 249.37,396.54 258.37,387.54 258.37,358.54
  region net NetC17_1: 312.99,-294.46 281.99,-294.46 281.99,-202.46 312.99,-202.46
  region net NetC22_1: 267.99,-56.46 236.99,-56.46 236.99,27.16 254.26,44.43 267.99,44.43
  region net NetC15_1: 314.37,-516.46 283.37,-516.46 283.37,-435.46 314.37,-435.46
  region net NetC15_2: 313.09,-417.29 282.09,-417.29 282.09,-308.91 313.09,-308.91
  pour cut-out: 327.37,-113.46 372.37,-113.46 372.37,6.54 268.37,6.54 268.37,-530.2 327.37,-530.2
  region net NetC19_2: 312.99,-56.46 281.99,-56.46 281.99,52.16 294.37,64.54 312.99,64.54
  pour cut-out: 328.37,121.54 193.37,121.54 193.37,-93.46 103.37,-93.46 103.37,126.54 38.37,126.54 38.37,466.54 323.37,466.54 328.37,466.54
  pour cut-out: 569.37,396.54 478.37,396.54 478.37,321.54 569.37,321.54
  pour cut-out: 680.37,201.54 533.37,201.54 513.37,181.54 513.37,41.54 589.37,-34.46 680.37,-34.46

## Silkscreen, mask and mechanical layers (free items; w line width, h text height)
Top Overlay:
  circle w3.94: c0,0 r1259.84
Bottom Overlay:
  text ".DOC_NUM  / R.DOC_REV" at -125,-995 h30
  text ".PCB_PN" at -410,-1000 h30
Mechanical 1:
  circle w3.94: c0,0 r1259.84
  circle w10: c0,0 r1377.95
Mechanical 4:
  drawing of 383 lines, arcs and shapes, not listed
  text "Layer" at 3267.97,4110 h44.73
  text "Name" at 3578.66,4110 h44.73
  text "Thickness" at 4575,4110 h44.73
  text "Constant" at 5064.55,4110 h44.73
  text "Board Layer Stack" at 5494.48,4110 h44.73
  text "Top Overlay" at 3578.66,4020.54 h44.73
  text "Top Solder" at 3578.66,3931.08 h44.73
  text "1.00mil" at 4575,3931.08 h44.73
  text "4" at 5064.55,3931.08 h44.73
  text "Top Surface Finish" at 3578.66,3841.61 h44.73
  text "0.79mil" at 4575,3841.61 h44.73
  text "1" at 3267.97,3752.15 h44.73
  text "Top Layer" at 3578.66,3752.15 h44.73
  text "1.38mil" at 4575,3752.15 h44.73
  text "Dielectric 1" at 3578.66,3662.69 h44.73
  text "5.10mil" at 4575,3662.69 h44.73
  text "4.3" at 5064.55,3662.69 h44.73
  text "Dielectric 2" at 3578.66,3573.23 h44.73
  text "5.10mil" at 4575,3573.23 h44.73
  text "4.3" at 5064.55,3573.23 h44.73
  text "2" at 3267.97,3483.77 h44.73
  text "Int1 (PWR)" at 3578.66,3483.77 h44.73
  text "1.38mil" at 4575,3483.77 h44.73
  text "Dielectric 3" at 3578.66,3394.3 h44.73
  text "28.00mil" at 4575,3394.3 h44.73
  text "4.8" at 5064.55,3394.3 h44.73
  text "3" at 3267.97,3304.84 h44.73
  text "Int2 (GND)" at 3578.66,3304.84 h44.73
  text "1.38mil" at 4575,3304.84 h44.73
  text "Dielectric 4" at 3578.66,3215.38 h44.73
  text "5.10mil" at 4575,3215.38 h44.73
  text "4.3" at 5064.55,3215.38 h44.73
  text "Dielectric 5" at 3578.66,3125.92 h44.73
  text "5.10mil" at 4575,3125.92 h44.73
  text "4.3" at 5064.55,3125.92 h44.73
  text "4" at 3267.97,3036.46 h44.73
  text "Bottom Layer" at 3578.66,3036.46 h44.73
  text "1.38mil" at 4575,3036.46 h44.73
  text "Bottom Surface Finish" at 3578.66,2946.99 h44.73
  text "0.79mil" at 4575,2946.99 h44.73
  text "Bottom Solder" at 3578.66,2857.53 h44.73
  text "1.00mil" at 4575,2857.53 h44.73
  text "4" at 5064.55,2857.53 h44.73
  text "Bottom Overlay" at 3578.66,2768.07 h44.73
  text ".Print_Date" at 3079.34,2290.91 h40
  text ".Print_Time" at 3850.14,2284.71 h40
  text "FABRICATION NOTES" at 3074.84,2198.76 h60
  text "1. PCB CONSTRUCTION: 4 LAYERS, AS SHOWN IN STACK-UP DETAIL." at 3349.87,2117.72 h60
  text "2. MATERIAL" at 3349.82,2022.12 h60
  text "A. LAMINATE: 0.059\" +/- 10%" at 3522.99,1909.49 h60
  text "B. 1 OZ COPPER ON EXTERNAL LAYERS, PLATED TO 1.5 OZ MIN. FINISHED WEIGHT." at 3517.09,1774.78 h60
  text "C. TOLERANCE: PER IPC-D-275" at 3437.36,1678.03 h60
  text "D. BONDING INTERLAYERS: PER IPC-2-110" at 3517.09,1623.9 h60
  text "E. ELECTROLESS NICKEL IMMERSION GOLD (ENIG) FINISH." at 3510.2,1511 h60
  text "3. PROCESSING TOLERANCES:" at 3358.73,1457.54 h60
  text "A. CONDUCTIVE PATTERN FRONT TO BACK, REGISTRATION +/- 0.005\"" at 3541.85,1376.5 h60
  text "B. MINIMUM AVERAGE PLATED THROUGH HOLE THICKNESS 0.001\" WITH NO READING LESS THAN 0.0004\"" at 3541.85,1281.54 h60
  text "C. FINISHED HOLE TOLERANCES AS FOLLOWS UNLESS OTHERWISE INDICATED:" at 3541.85,1193.54 h60
  text "PLATED +/- 0.003" at 3704.58,1105.54 h60
  text "NON-PLATED: +/- 0.003" at 3704.69,1017.54 h60
  text "D. MINIMUM ANNULAR RING FOR VIAS 0.006\"" at 3541.85,929.54 h60
  text "E. MINIMUM CONDUCTOR WIDTH 0.006\"" at 3541.85,841.54 h60
  text "F. MINIMUM INTER-CONDUCTOR SPACE 0.006\"" at 3541.85,753.54 h60
  text "4. DIMENSIONS:" at 3362.56,651.46 h60
  text "A. INSIDE CORNER RADII <= 1.0MM" at 3539.72,556.97 h60
  text "5. WARP AND TWIST:" at 3371.42,456.58 h60
  text "A. WITHIN 0.010\" PER INCH MAX" at 3532.66,365.97 h60
  text "D. SOLDER MASK TO ETCH REGISTRATION WITHIN 0.003\" TOTAL" at 3545.77,290.44 h60
  text "6. SOLDER MASK" at 3099.61,130.3 h60
  text "A. LPI SMOBC 2 SIDE, PER IPC-SM-840, REV C, CLASS H" at 3282.72,49.26 h60
  text "B. COLOR = GREEN" at 3282.72,-45.7 h60
  text "C. NO MASK ALLOWED ON TERMINAL AREAS, COMPONENT SOLDER PADS & TEST POINTS" at 3282.84,-148.74 h60
  text "D. MASK OPENINGS THAT ARE 1:1 WITH THE COPPER PADS SHOULD BE ADJUSTED BY THE FABRICATOR AS NEEDED" at 3282.72,-306.84 h60
  text "7. SILKSCREEN:" at 3099.61,-397.7 h60
  text "A. NON-CONDUCTIVE WHITE EPOXY INK ON BOTH SIDES" at 3271.02,-472.56 h60
  text "B. NOMENCLATURE SHALL BE COMPLETE AND LEGIBLE PER IPC-D-275 AND IPC-A-600" at 3275.95,-577.87 h60
  text "ON SOLDER SIDE OF PCB ANYWHERE FOR EACH LOT" at 3351.73,-646.77 h60
  text "C. MERGE SOLDERMASK AND SILKSCREEN - NO SILKSCREEN ALLOWED ON EXPOSED COPPER" at 3280.87,-740.28 h60
  text "9. BOARDS TO BE 100% TESTED TO IPC-D-3506A NETLIST - NO REWORK" at 3071.93,-834.84 h60
  text "For any questions please contact Mikhail Fridberg - 781-327-2037 - fridberg@adspconsulting.com" at 3088.66,-944.09 h60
